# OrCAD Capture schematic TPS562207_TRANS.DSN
size E
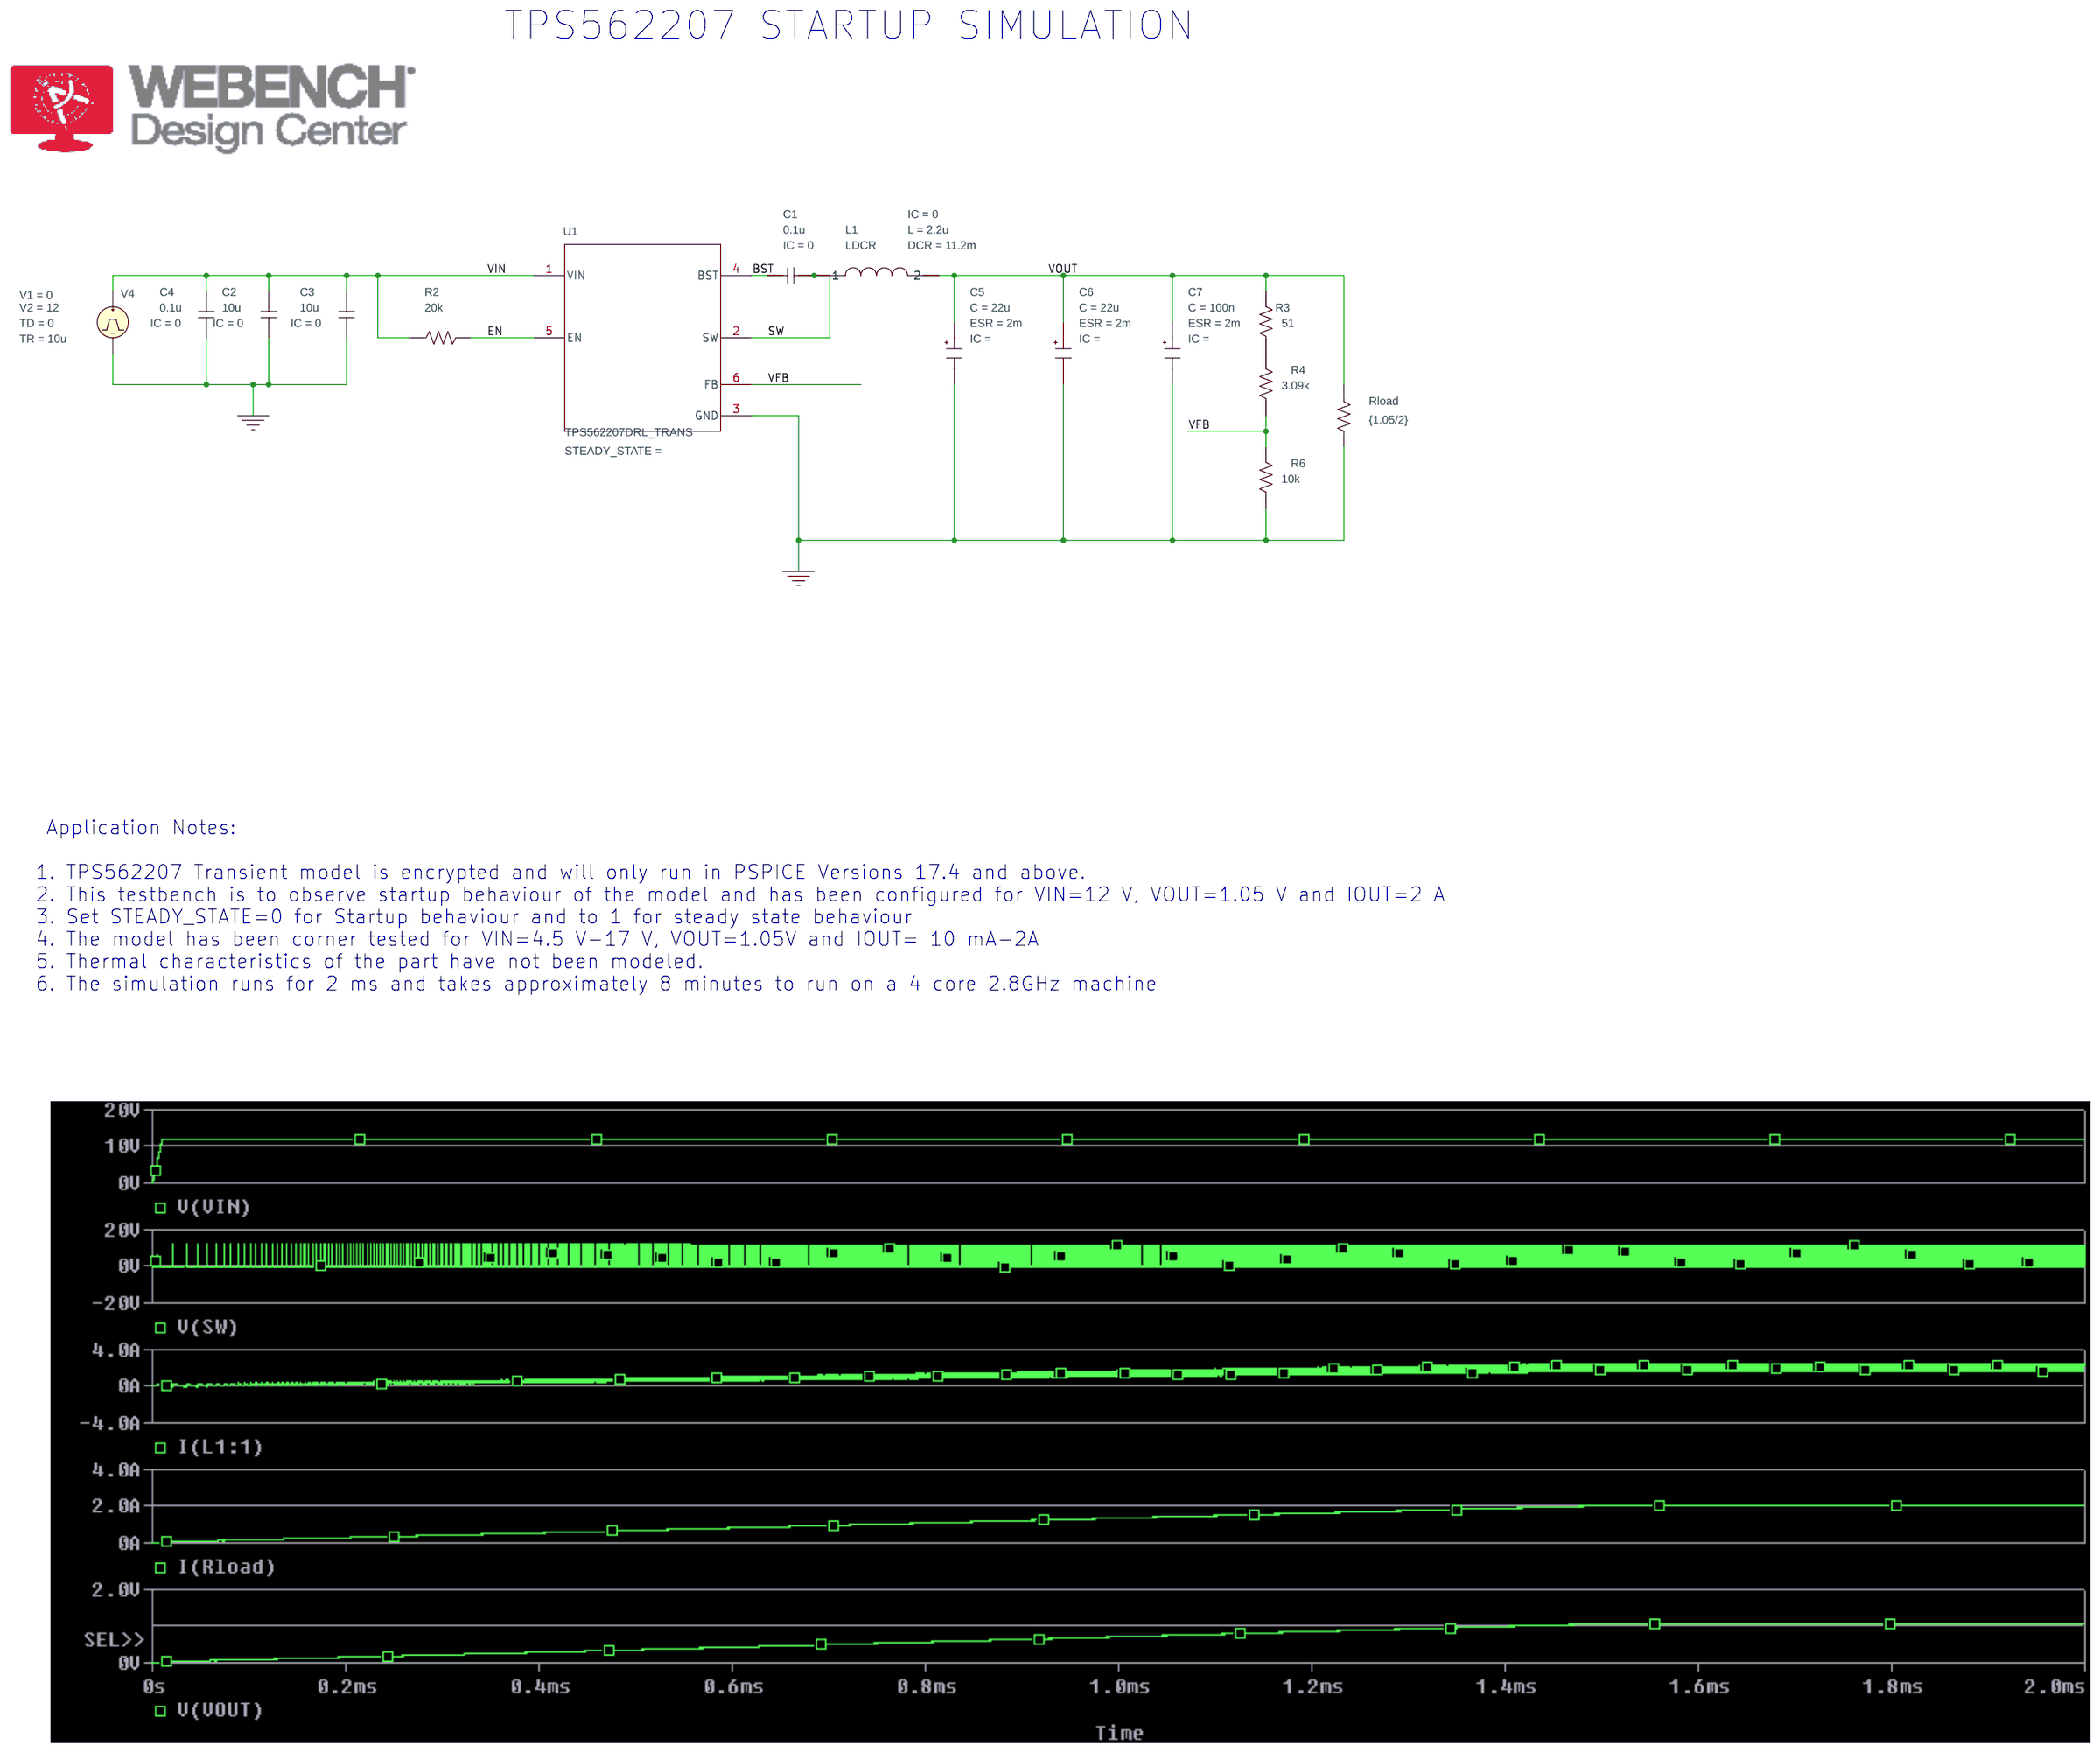
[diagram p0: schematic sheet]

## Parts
C1  0.1u  [RAD/CK05]
C2  10u  [RAD/CK05]
C3  10u  [RAD/CK05]
C4  0.1u  [RAD/CK05]
C5  CESR
C6  CESR
C7  CESR
L1  LDCR
R2  20k  [AX/RC05]
R3  51  [AX/RC05]
R4  3.09k  [AX/RC05]
R6  10k  [AX/RC05]
Rload  {1.05/2}  [AX/RC05]
U1  TPS562207DRL_TRANS  [DRL0006A]
V4  VPULSE

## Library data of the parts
C1-C4 = C: IC: 0
C5 C6 = CESR_0: C: 22u; ESR: 2m; PSpiceTemplate: X^@REFDES %IN %OUT @MODEL PARAMS:  ?C|C=@C||C=100u|  ?ESR|ESR=@ESR||ESR=0.01| ?X|X=@X||X=2|  ?IC|IC=@IC||IC=2|; X: 1
C7 = CESR_0: C: 100n; ESR: 2m; PSpiceTemplate: X^@REFDES %IN %OUT @MODEL PARAMS:  ?C|C=@C||C=100u|  ?ESR|ESR=@ESR||ESR=0.01| ?X|X=@X||X=2|  ?IC|IC=@IC||IC=2|; X: 1
L1 = LDCR: DCR: 11.2m; IC: 0; L: 2.2u
R2-R4 R6 Rload = R
U1 = TPS562207DRL_TRANS
V4 = VPULSE: TD: 0; TR: 10u; V1: 0; V2: 12

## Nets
VIN: C2.1 C3.1 C4.1 R2.1 U1.1(VIN) V4.1(+)
0: C2.2 C3.2 C4.2 C5.3(OUT) C6.3(OUT) C7.3(OUT) R6.1 Rload.2 U1.3(GND) V4.2(-)
BST: C1.2 U1.4(BST)
EN: R2.2 U1.5(EN)
SW: C1.1 L1.1 U1.2(SW)
VFB: R4.1 R6.2 U1.6(FB)
VOUT: C5.1(IN) C6.1(IN) C7.1(IN) L1.2 R3.2 Rload.1
N16793093: R3.1 R4.2

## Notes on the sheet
- TPS562207 STARTUP SIMULATION
- Application Notes:
  1. TPS562207 Transient model is encrypted and will only run in PSPICE Versions 17.4 and above.
  2. This testbench is to observe startup behaviour of the model and has been configured for VIN=12 V, VOUT=1.05 V and IOUT=2 A
  3. Set STEADY_STATE=0 for Startup behaviour and to 1 for steady state behaviour
  4. The model has been corner tested for VIN=4.5 V-17 V, VOUT=1.05V and IOUT= 10 mA-2A
  5. Thermal characteristics of the part have not been modeled.
  6. The simulation runs for 2 ms and takes approximately 8 minutes to run on a 4 core 2.8GHz machine
